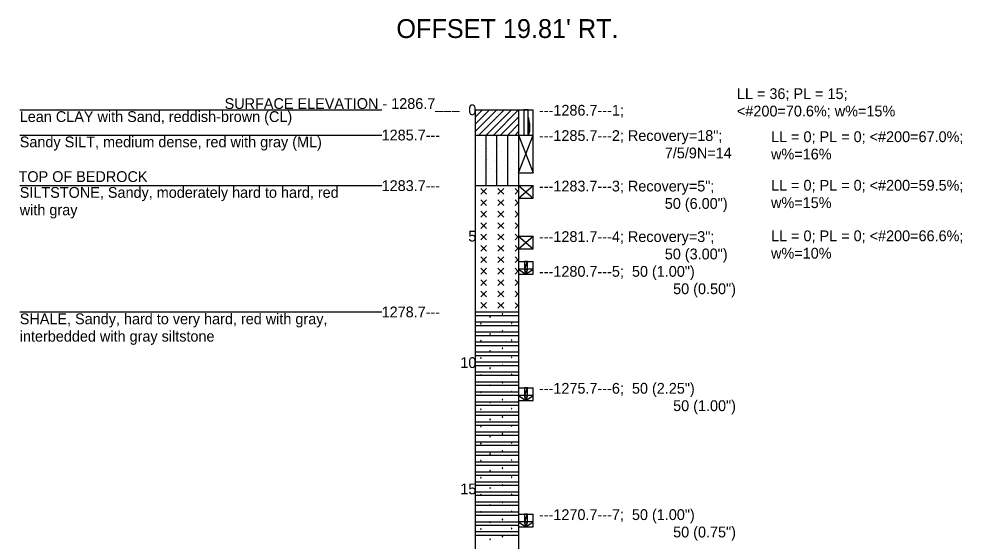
# Model space of a CAD drawing. Extents: x -6 to 173, y 24 to 64.
# Drawn here: x 96.45 to 107.3, y 44.56 to 50.57 of the extents above; entities that cross this region are included whole.
import ezdxf

# ---------------------------------------------------------------- set-up
doc = ezdxf.new("R2010")
doc.units = 0

# ---------------------------------------------------------------- blocks, each defined once
blk = doc.blocks.new('POINT_DISPLAY')
blk.add_line((0, 0), (0, 0))

msp = doc.modelspace()

# ---------------------------------------------------------------- linework, layer by layer
for points in [[(96.46, 49.524), (100.626, 49.524)], [(101.698, 49.441), (101.781, 49.524)], [(101.698, 49.358), (101.864, 49.524)], [(101.698, 49.274), (101.948, 49.524)], [(101.698, 49.524), (101.698, 39.059)], [(101.698, 49.524), (102.198, 49.524)], [(101.74, 49.234), (102.031, 49.524)], [(101.824, 49.234), (102.114, 49.524)], [(101.907, 49.234), (102.198, 49.524)], [(102.198, 49.524), (102.364, 49.524)], [(102.198, 49.524), (102.198, 39.059)], [(102.364, 49.234), (102.364, 49.524)], [(101.99, 49.234), (102.198, 49.441)], [(102.074, 49.234), (102.198, 49.358)], [(102.157, 49.234), (102.198, 49.274)], [(96.46, 49.234), (100.626, 49.234)], [(101.698, 49.234), (102.198, 49.234)], [(101.823, 48.652), (101.823, 49.234)], [(101.948, 48.652), (101.948, 49.234)], [(102.073, 48.652), (102.073, 49.234)], [(102.198, 49.234), (102.364, 49.234)], [(102.198, 49.234), (102.364, 48.798)], [(102.198, 48.798), (102.364, 49.234)], [(102.198, 49.234), (102.364, 49.234)], [(102.364, 48.798), (102.364, 49.234)], [(102.198, 48.798), (102.364, 48.798)], [(96.46, 48.652), (100.626, 48.652)], [(101.698, 48.652), (102.198, 48.652)], [(101.829, 48.62), (101.763, 48.554)], [(101.763, 48.62), (101.829, 48.554)], [(102.026, 48.62), (101.96, 48.554)], [(101.96, 48.62), (102.026, 48.554)], [(102.157, 48.62), (102.198, 48.579)], [(102.198, 48.652), (102.364, 48.507)], [(102.198, 48.507), (102.364, 48.652)], [(102.198, 48.652), (102.364, 48.652)], [(102.364, 48.507), (102.364, 48.652)], [(102.198, 48.595), (102.157, 48.554)], [(102.198, 48.507), (102.364, 48.507)], [(101.829, 48.488), (101.763, 48.423)], [(101.763, 48.488), (101.829, 48.423)], [(102.026, 48.488), (101.96, 48.423)], [(101.96, 48.488), (102.026, 48.423)], [(102.157, 48.488), (102.198, 48.448)], [(102.198, 48.463), (102.157, 48.423)], [(101.829, 48.357), (101.763, 48.291)], [(101.763, 48.357), (101.829, 48.291)], [(102.026, 48.357), (101.96, 48.291)], [(101.96, 48.357), (102.026, 48.291)], [(102.157, 48.357), (102.198, 48.316)], [(102.198, 48.332), (102.157, 48.291)], [(101.829, 48.226), (101.763, 48.16)], [(101.763, 48.226), (101.829, 48.16)], [(102.026, 48.226), (101.96, 48.16)], [(101.96, 48.226), (102.026, 48.16)], [(102.157, 48.226), (102.198, 48.185)], [(102.198, 48.201), (102.157, 48.16)], [(101.829, 48.095), (101.763, 48.029)], [(101.763, 48.095), (101.829, 48.029)], [(102.026, 48.095), (101.96, 48.029)], [(101.96, 48.095), (102.026, 48.029)], [(102.157, 48.095), (102.198, 48.054)], [(102.198, 48.07), (102.157, 48.029)], [(102.198, 48.071), (102.364, 47.926)], [(102.198, 47.926), (102.364, 48.071)], [(102.198, 48.071), (102.364, 48.071)], [(102.364, 47.926), (102.364, 48.071)], [(101.829, 47.963), (101.763, 47.898)], [(101.763, 47.963), (101.829, 47.898)], [(102.026, 47.963), (101.96, 47.898)], [(101.96, 47.963), (102.026, 47.898)], [(102.157, 47.963), (102.198, 47.923)], [(102.198, 47.938), (102.157, 47.898)], [(102.198, 47.926), (102.364, 47.926)], [(101.829, 47.832), (101.763, 47.767)], [(101.763, 47.832), (101.829, 47.767)], [(102.026, 47.832), (101.96, 47.767)], [(101.96, 47.832), (102.026, 47.767)], [(102.157, 47.832), (102.198, 47.791)], [(102.198, 47.807), (102.157, 47.767)], [(102.198, 47.78), (102.364, 47.78)], [(102.364, 47.635), (102.364, 47.78)], [(101.829, 47.701), (101.763, 47.635)], [(101.763, 47.701), (101.829, 47.635)], [(102.026, 47.701), (101.96, 47.635)], [(101.96, 47.701), (102.026, 47.635)], [(102.157, 47.701), (102.198, 47.66)], [(102.198, 47.676), (102.157, 47.635)], [(102.198, 47.635), (102.364, 47.635)], [(101.829, 47.57), (101.763, 47.504)], [(101.763, 47.57), (101.829, 47.504)], [(102.026, 47.57), (101.96, 47.504)], [(101.96, 47.57), (102.026, 47.504)], [(102.157, 47.57), (102.198, 47.529)], [(102.198, 47.545), (102.157, 47.504)], [(101.829, 47.438), (101.763, 47.373)], [(101.763, 47.438), (101.829, 47.373)], [(102.026, 47.438), (101.96, 47.373)], [(101.96, 47.438), (102.026, 47.373)], [(102.157, 47.438), (102.198, 47.398)], [(102.198, 47.414), (102.157, 47.373)], [(101.829, 47.307), (101.763, 47.242)], [(101.763, 47.307), (101.829, 47.242)], [(102.026, 47.307), (101.96, 47.242)], [(101.96, 47.307), (102.026, 47.242)], [(102.157, 47.307), (102.162, 47.302), (102.198, 47.267)], [(96.46, 47.199), (100.626, 47.199)], [(101.698, 47.199), (102.198, 47.199)], [(101.698, 47.199), (102.198, 47.199)], [(102.198, 47.282), (102.176, 47.261), (102.157, 47.242)], [(101.698, 47.16), (102.198, 47.16)], [(101.873, 47.143), (101.871, 47.146), (101.868, 47.146), (101.866, 47.143), (101.868, 47.14), (101.871, 47.14), (101.873, 47.143)], [(102.015, 47.175), (102.014, 47.178), (102.01, 47.178), (102.009, 47.175), (102.01, 47.172), (102.014, 47.172), (102.015, 47.175)], [(101.698, 47.084), (102.198, 47.084)], [(101.698, 47.045), (102.198, 47.045)], [(101.768, 47.064), (101.766, 47.067), (101.763, 47.067), (101.761, 47.064), (101.763, 47.061), (101.766, 47.061), (101.768, 47.064)], [(102.015, 46.978), (102.014, 46.981), (102.01, 46.981), (102.009, 46.978), (102.01, 46.975), (102.014, 46.975), (102.015, 46.978)], [(102.121, 47.071), (102.119, 47.073), (102.116, 47.073), (102.114, 47.071), (102.116, 47.068), (102.119, 47.068), (102.121, 47.071)], [(101.698, 46.969), (102.198, 46.969)], [(101.698, 46.93), (102.198, 46.93)], [(101.768, 46.867), (101.766, 46.87), (101.763, 46.87), (101.761, 46.867), (101.763, 46.864), (101.766, 46.864), (101.768, 46.867)], [(101.873, 46.946), (101.871, 46.949), (101.868, 46.949), (101.866, 46.946), (101.868, 46.943), (101.871, 46.943), (101.873, 46.946)], [(102.121, 46.874), (102.119, 46.877), (102.116, 46.877), (102.114, 46.874), (102.116, 46.871), (102.119, 46.871), (102.121, 46.874)], [(101.698, 46.854), (102.198, 46.854)], [(101.698, 46.815), (102.198, 46.815)], [(102.015, 46.781), (102.014, 46.784), (102.01, 46.784), (102.009, 46.781), (102.01, 46.778), (102.014, 46.778), (102.015, 46.781)], [(101.698, 46.74), (102.198, 46.74)], [(101.698, 46.7), (102.198, 46.7)], [(101.768, 46.67), (101.766, 46.673), (101.763, 46.673), (101.761, 46.67), (101.763, 46.668), (101.766, 46.668), (101.768, 46.67)], [(101.873, 46.749), (101.871, 46.752), (101.868, 46.752), (101.866, 46.749), (101.868, 46.747), (101.871, 46.747), (101.873, 46.749)], [(102.121, 46.677), (102.119, 46.68), (102.116, 46.68), (102.114, 46.677), (102.116, 46.674), (102.119, 46.674), (102.121, 46.677)], [(101.698, 46.625), (102.198, 46.625)], [(101.698, 46.585), (102.198, 46.585)], [(101.873, 46.552), (101.871, 46.555), (101.868, 46.555), (101.866, 46.553), (101.868, 46.55), (101.871, 46.55), (101.873, 46.552)], [(102.015, 46.584), (102.014, 46.587), (102.01, 46.587), (102.009, 46.584), (102.01, 46.582), (102.014, 46.582), (102.015, 46.584)], [(101.698, 46.51), (102.198, 46.51)], [(101.698, 46.471), (102.198, 46.471)], [(101.768, 46.474), (101.766, 46.476), (101.763, 46.476), (101.761, 46.474), (101.763, 46.471), (101.766, 46.471), (101.768, 46.474)], [(102.121, 46.48), (102.119, 46.483), (102.116, 46.483), (102.114, 46.48), (102.116, 46.477), (102.119, 46.477), (102.121, 46.48)], [(101.698, 46.395), (102.198, 46.395)], [(101.698, 46.356), (102.198, 46.356)], [(101.873, 46.356), (101.871, 46.359), (101.868, 46.359), (101.866, 46.356), (101.868, 46.353), (101.871, 46.353), (101.873, 46.356)], [(102.015, 46.388), (102.014, 46.39), (102.01, 46.39), (102.009, 46.388), (102.01, 46.385), (102.014, 46.385), (102.015, 46.388)], [(102.198, 46.327), (102.364, 46.327)], [(102.364, 46.181), (102.364, 46.327)], [(101.698, 46.28), (102.198, 46.28)], [(101.698, 46.241), (102.198, 46.241)], [(101.768, 46.277), (101.766, 46.28), (101.763, 46.28), (101.761, 46.277), (101.763, 46.274), (101.766, 46.274), (101.768, 46.277)], [(102.121, 46.283), (102.119, 46.286), (102.116, 46.286), (102.114, 46.283), (102.116, 46.28), (102.119, 46.28), (102.121, 46.283)], [(101.698, 46.165), (102.198, 46.165)], [(101.698, 46.126), (102.198, 46.126)], [(101.873, 46.159), (101.871, 46.162), (101.868, 46.162), (101.866, 46.159), (101.868, 46.156), (101.871, 46.156), (101.873, 46.159)], [(102.015, 46.191), (102.014, 46.194), (102.01, 46.194), (102.009, 46.191), (102.01, 46.188), (102.014, 46.188), (102.015, 46.191)], [(102.198, 46.181), (102.364, 46.181)], [(101.698, 46.051), (102.198, 46.051)], [(101.698, 46.011), (102.198, 46.011)], [(101.768, 46.08), (101.766, 46.083), (101.763, 46.083), (101.761, 46.08), (101.763, 46.077), (101.766, 46.077), (101.768, 46.08)], [(102.121, 46.086), (102.119, 46.089), (102.116, 46.089), (102.114, 46.086), (102.116, 46.084), (102.119, 46.084), (102.121, 46.086)], [(101.698, 45.936), (102.198, 45.936)], [(101.698, 45.896), (102.198, 45.896)], [(101.873, 45.962), (101.871, 45.965), (101.868, 45.965), (101.866, 45.962), (101.868, 45.959), (101.871, 45.959), (101.873, 45.962)], [(102.015, 45.994), (102.014, 45.997), (102.01, 45.997), (102.009, 45.994), (102.01, 45.991), (102.014, 45.991), (102.015, 45.994)], [(102.121, 45.89), (102.119, 45.892), (102.116, 45.892), (102.114, 45.89), (102.116, 45.887), (102.119, 45.887), (102.121, 45.89)], [(101.698, 45.821), (102.198, 45.821)], [(101.768, 45.883), (101.766, 45.886), (101.763, 45.886), (101.761, 45.883), (101.763, 45.88), (101.766, 45.88), (101.768, 45.883)], [(102.015, 45.797), (102.014, 45.8), (102.01, 45.8), (102.009, 45.797), (102.01, 45.794), (102.014, 45.794), (102.015, 45.797)], [(101.698, 45.782), (102.198, 45.782)], [(101.698, 45.706), (102.198, 45.706)], [(101.768, 45.686), (101.766, 45.689), (101.763, 45.689), (101.761, 45.686), (101.763, 45.683), (101.766, 45.683), (101.768, 45.686)], [(101.873, 45.765), (101.871, 45.768), (101.868, 45.768), (101.866, 45.765), (101.868, 45.762), (101.871, 45.762), (101.873, 45.765)], [(102.121, 45.693), (102.119, 45.696), (102.116, 45.696), (102.114, 45.693), (102.116, 45.69), (102.119, 45.69), (102.121, 45.693)], [(101.698, 45.667), (102.198, 45.667)], [(101.698, 45.591), (102.198, 45.591)], [(101.873, 45.568), (101.871, 45.571), (101.868, 45.571), (101.866, 45.568), (101.868, 45.565), (101.871, 45.565), (101.873, 45.568)], [(102.015, 45.6), (102.014, 45.603), (102.01, 45.603), (102.009, 45.6), (102.01, 45.597), (102.014, 45.597), (102.015, 45.6)], [(101.698, 45.552), (102.198, 45.552)], [(101.698, 45.476), (102.198, 45.476)], [(101.768, 45.489), (101.766, 45.492), (101.763, 45.492), (101.761, 45.489), (101.763, 45.486), (101.766, 45.486), (101.768, 45.489)], [(102.121, 45.496), (102.119, 45.499), (102.116, 45.499), (102.114, 45.496), (102.116, 45.493), (102.119, 45.493), (102.121, 45.496)], [(101.698, 45.437), (102.198, 45.437)], [(101.698, 45.362), (102.198, 45.362)], [(101.873, 45.371), (101.871, 45.374), (101.868, 45.374), (101.866, 45.371), (101.868, 45.369), (101.871, 45.369), (101.873, 45.371)], [(102.015, 45.403), (102.014, 45.406), (102.01, 45.406), (102.009, 45.403), (102.01, 45.4), (102.014, 45.4), (102.015, 45.403)], [(101.698, 45.322), (102.198, 45.322)], [(101.698, 45.247), (102.198, 45.247)], [(101.768, 45.292), (101.766, 45.295), (101.763, 45.295), (101.761, 45.292), (101.763, 45.29), (101.766, 45.29), (101.768, 45.292)], [(102.121, 45.299), (102.119, 45.302), (102.116, 45.302), (102.114, 45.299), (102.116, 45.296), (102.119, 45.296), (102.121, 45.299)], [(101.698, 45.207), (102.198, 45.207)], [(101.873, 45.175), (101.871, 45.177), (101.868, 45.177), (101.866, 45.175), (101.868, 45.172), (101.871, 45.172), (101.873, 45.175)], [(102.015, 45.206), (102.014, 45.209), (102.01, 45.209), (102.009, 45.206), (102.01, 45.204), (102.014, 45.204), (102.015, 45.206)], [(101.698, 45.132), (102.198, 45.132)], [(101.698, 45.093), (102.198, 45.093)], [(101.768, 45.096), (101.766, 45.098), (101.763, 45.098), (101.761, 45.096), (101.763, 45.093), (101.766, 45.093), (101.768, 45.096)], [(102.121, 45.102), (102.119, 45.105), (102.116, 45.105), (102.114, 45.102), (102.116, 45.099), (102.119, 45.099), (102.121, 45.102)], [(101.698, 45.017), (102.198, 45.017)], [(101.698, 44.978), (102.198, 44.978)], [(101.873, 44.978), (101.871, 44.981), (101.868, 44.981), (101.866, 44.978), (101.868, 44.975), (101.871, 44.975), (101.873, 44.978)], [(102.015, 45.01), (102.014, 45.012), (102.01, 45.012), (102.009, 45.01), (102.01, 45.007), (102.014, 45.007), (102.015, 45.01)], [(101.698, 44.902), (102.198, 44.902)], [(101.698, 44.863), (102.198, 44.863)], [(101.768, 44.899), (101.766, 44.902), (101.763, 44.902), (101.761, 44.899), (101.763, 44.896), (101.766, 44.896), (101.768, 44.899)], [(102.015, 44.813), (102.014, 44.816), (102.01, 44.816), (102.009, 44.813), (102.01, 44.81), (102.014, 44.81), (102.015, 44.813)], [(102.121, 44.905), (102.119, 44.908), (102.116, 44.908), (102.114, 44.905), (102.116, 44.902), (102.119, 44.902), (102.121, 44.905)], [(102.198, 44.873), (102.364, 44.873)], [(102.364, 44.728), (102.364, 44.873)], [(101.698, 44.787), (102.198, 44.787)], [(101.698, 44.748), (102.198, 44.748)], [(101.768, 44.702), (101.766, 44.705), (101.763, 44.705), (101.761, 44.702), (101.763, 44.699), (101.766, 44.699), (101.768, 44.702)], [(101.873, 44.781), (101.871, 44.784), (101.868, 44.784), (101.866, 44.781), (101.868, 44.778), (101.871, 44.778), (101.873, 44.781)], [(102.121, 44.708), (102.119, 44.711), (102.116, 44.711), (102.114, 44.708), (102.116, 44.706), (102.119, 44.706), (102.121, 44.708)], [(102.198, 44.728), (102.364, 44.728)], [(101.698, 44.673), (102.198, 44.673)], [(101.698, 44.633), (102.198, 44.633)], [(102.015, 44.616), (102.014, 44.619), (102.01, 44.619), (102.009, 44.616), (102.01, 44.613), (102.014, 44.613), (102.015, 44.616)], [(101.873, 44.584), (101.871, 44.587), (101.868, 44.587), (101.866, 44.584), (101.868, 44.581), (101.871, 44.581), (101.873, 44.584)]]:
    msp.add_lwpolyline(points)
for points in [[(102.256, 49.524), (102.256, 49.234), (102.306, 49.234), (102.306, 49.524)], [(102.321, 49.358), (102.315, 49.399), (102.306, 49.439), (102.321, 49.358)], [(102.306, 49.439), (102.306, 49.234), (102.321, 49.358), (102.306, 49.439)], [(102.306, 49.234), (102.321, 49.274), (102.321, 49.358), (102.306, 49.234)], [(102.306, 49.234), (102.315, 49.234), (102.321, 49.274), (102.306, 49.234)], [(102.321, 49.274), (102.323, 49.316), (102.321, 49.358), (102.321, 49.274)], [(102.264, 47.693), (102.298, 47.693), (102.298, 47.78), (102.264, 47.693)], [(102.264, 47.693), (102.298, 47.78), (102.264, 47.78), (102.264, 47.693)], [(102.264, 47.693), (102.198, 47.693), (102.281, 47.635), (102.264, 47.693)], [(102.264, 47.693), (102.281, 47.635), (102.298, 47.693), (102.264, 47.693)], [(102.281, 47.635), (102.364, 47.693), (102.298, 47.693), (102.281, 47.635)], [(102.264, 46.24), (102.298, 46.24), (102.298, 46.327), (102.264, 46.24)], [(102.264, 46.24), (102.298, 46.327), (102.264, 46.327), (102.264, 46.24)], [(102.264, 46.24), (102.198, 46.24), (102.281, 46.181), (102.264, 46.24)], [(102.264, 46.24), (102.281, 46.181), (102.298, 46.24), (102.264, 46.24)], [(102.281, 46.181), (102.364, 46.24), (102.298, 46.24), (102.281, 46.181)], [(102.264, 44.786), (102.298, 44.786), (102.298, 44.873), (102.264, 44.786)], [(102.264, 44.786), (102.298, 44.873), (102.264, 44.873), (102.264, 44.786)], [(102.264, 44.786), (102.198, 44.786), (102.281, 44.728), (102.264, 44.786)], [(102.264, 44.786), (102.281, 44.728), (102.298, 44.786), (102.264, 44.786)], [(102.281, 44.728), (102.364, 44.786), (102.298, 44.786), (102.281, 44.728)]]:
    msp.add_lwpolyline(points, close=True)

# ---------------------------------------------------------------- block references
at = {"xscale": 0.01, "yscale": 0.01}
for p in [(101.737, 49.508), (101.803, 49.474), (101.903, 49.508), (102.003, 49.474), (102.123, 49.491), (101.703, 49.441), (101.77, 49.408), (101.837, 49.374), (101.926, 49.444), (101.97, 49.408), (102.07, 49.408), (102.17, 49.441), (101.737, 49.341), (101.77, 49.274), (101.903, 49.308), (101.987, 49.332), (102.003, 49.274), (102.122, 49.256), (102.137, 49.341), (101.703, 49.15), (101.737, 49.217), (101.803, 49.184), (101.837, 49.241), (101.903, 49.217), (101.926, 49.153), (102.003, 49.184), (102.123, 49.2), (102.17, 49.15), (101.737, 49.05), (101.77, 49.117), (101.837, 49.084), (101.97, 49.117), (101.987, 49.041), (102.07, 49.117), (102.137, 49.05), (101.77, 48.984), (101.837, 48.95), (101.903, 49.017), (101.922, 48.94), (102.003, 48.984), (102.122, 48.966), (101.703, 48.917), (101.803, 48.884), (101.87, 48.85), (101.973, 48.87), (102.037, 48.884), (102.103, 48.85), (102.17, 48.917), (101.703, 48.717), (101.77, 48.784), (101.903, 48.75), (101.937, 48.817), (102.016, 48.784), (102.07, 48.717), (102.137, 48.784), (101.803, 48.684), (101.97, 48.684)]:
    msp.add_blockref('POINT_DISPLAY', p, dxfattribs=at)

# ---------------------------------------------------------------- texts
for s, height, p in [("OFFSET 19.81' RT.", 0.217, (100.792, 50.35)), ('LL = 36; PL = 15;', 0.124, (104.709, 49.648)), ('SURFACE ELEVATION - 1286.7___', 0.124, (98.816, 49.534)), ('0', 0.124, (101.619, 49.462)), ('---1286.7---1;', 0.124, (102.432, 49.457)), ('Lean CLAY with Sand, reddish-brown (CL)', 0.124, (96.46, 49.384)), ('<#200=70.6%; w%=15%', 0.124, (104.709, 49.448)), ('1285.7---', 0.124, (100.622, 49.172)), ('---1285.7---2; Recovery=18";', 0.124, (102.432, 49.166)), ('LL = 0; PL = 0; <#200=67.0%;', 0.124, (105.101, 49.153)), ('Sandy SILT, medium dense, red with gray (ML)', 0.124, (96.46, 49.093)), ('7/5/9N=14', 0.124, (103.879, 48.966)), ('w%=16%', 0.124, (105.101, 48.953)), ('TOP OF BEDROCK', 0.124, (96.446, 48.694)), ('1283.7---', 0.124, (100.622, 48.59)), ('LL = 0; PL = 0; <#200=59.5%;', 0.124, (105.101, 48.594)), ('SILTSTONE, Sandy, moderately hard to hard, red', 0.124, (96.46, 48.512)), ('---1283.7---3; Recovery=5";', 0.124, (102.432, 48.585)), ('50 (6.00")', 0.124, (103.879, 48.385)), ('w%=15%', 0.124, (105.101, 48.394)), ('with gray', 0.124, (96.46, 48.312)), ('5', 0.124, (101.619, 48.009)), ('---1281.7---4; Recovery=3";', 0.124, (102.432, 48.004)), ('LL = 0; PL = 0; <#200=66.6%;', 0.124, (105.101, 48.013)), ('50 (3.00")', 0.124, (103.879, 47.804)), ('w%=10%', 0.124, (105.101, 47.813)), ('---1280.7---5;  50 (1.00")', 0.124, (102.432, 47.604)), ('50 (0.50")', 0.124, (103.975, 47.404)), ('1278.7---', 0.124, (100.622, 47.137)), ('SHALE, Sandy, hard to very hard, red with gray,', 0.124, (96.46, 47.058)), ('interbedded with gray siltstone', 0.124, (96.46, 46.858)), ('10', 0.124, (101.527, 46.555)), ('---1275.7---6;  50 (2.25")', 0.124, (102.432, 46.259)), ('50 (1.00")', 0.124, (103.975, 46.059)), ('15', 0.124, (101.527, 45.102)), ('---1270.7---7;  50 (1.00")', 0.124, (102.432, 44.806)), ('50 (0.75")', 0.124, (103.975, 44.606))]:
    msp.add_text(s, height=height).set_placement(p)

doc.saveas('drawing.dxf')
